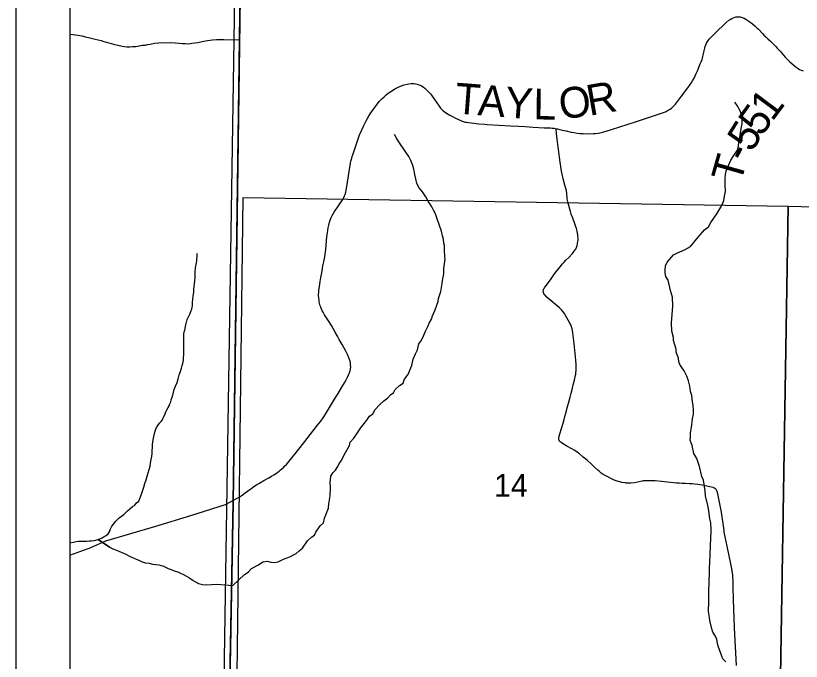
# Model space of a CAD drawing. Extents: x -1.2 to 34, y -8.5 to 22.
# Drawn here: x 2 to 3.451, y 15.827 to 17.02 of the extents above; entities that cross this region are included whole.
import ezdxf

# ---------------------------------------------------------------- set-up
doc = ezdxf.new("R2010")
doc.units = 0
for name, color, linetype in [('DV_X_County_Line', 7, 'Continuous'), ('GM_X_Minor_River', 7, 'Continuous'), ('GM_X_Section', 7, 'Continuous'), ('GM_X_Section_Text', 7, 'Continuous'), ('GM_X_Township_Road', 7, 'Continuous'), ('GM_X_Township_Road_Text', 7, 'Continuous'), ('GM_X_Unincorporated_Text', 7, 'Continuous'), ('SH_Cut_Line', 7, 'Continuous'), ('SH_Data', 7, 'Continuous')]:
    doc.layers.add(name, color=color, linetype=linetype)

msp = doc.modelspace()

# ---------------------------------------------------------------- linework, layer by layer
at = {"layer": 'DV_X_County_Line'}
msp.add_line((2.3586, 14.1), (2.465, 20.9), dxfattribs=at)
at = {"layer": 'GM_X_Minor_River'}
for points in [[(2.1, 16.9857), (2.106, 16.9851), (2.1147, 16.9841), (2.1223, 16.9827), (2.1292, 16.9809), (2.1368, 16.9794), (2.1421, 16.978), (2.1471, 16.9765), (2.1524, 16.9755), (2.1581, 16.974), (2.1631, 16.9726), (2.168, 16.9711), (2.1722, 16.97), (2.1764, 16.9689), (2.1806, 16.9675), (2.1966, 16.9639), (2.2008, 16.9631), (2.2053, 16.9628), (2.2107, 16.9629), (2.216, 16.9633), (2.2217, 16.9634), (2.2281, 16.9642), (2.2345, 16.9655), (2.2395, 16.9659), (2.2436, 16.9667), (2.2482, 16.9675), (2.2565, 16.9692), (2.2637, 16.97), (2.2709, 16.9705), (2.2781, 16.9702), (2.2861, 16.9703), (2.2944, 16.97), (2.302, 16.9693), (2.3081, 16.969), (2.313, 16.9687), (2.3184, 16.9684), (2.3222, 16.9688), (2.3256, 16.9693), (2.3309, 16.9697), (2.3366, 16.9705), (2.3445, 16.9722), (2.3543, 16.9742), (2.3638, 16.9754), (2.371, 16.9759), (2.3767, 16.9764), (2.3809, 16.9764), (2.3847, 16.9761), (2.4143, 16.9753)], [(3.2152, 16.4254), (3.212, 16.4375), (3.2117, 16.4528), (3.2126, 16.468), (3.2139, 16.4836), (3.2133, 16.5), (3.2097, 16.5121), (3.2057, 16.5315), (3.2014, 16.5383), (3.2002, 16.5451), (3.1997, 16.5504), (3.2007, 16.558), (3.2037, 16.5649), (3.2152, 16.5784), (3.2216, 16.5812), (3.2314, 16.5859), (3.237, 16.5883), (3.2468, 16.5938), (3.2609, 16.6107), (3.2725, 16.6242), (3.28, 16.6297), (3.2844, 16.6381), (3.2951, 16.6543), (3.3044, 16.6697), (3.308, 16.6785), (3.3094, 16.6869), (3.3112, 16.6953), (3.3106, 16.7074), (3.3105, 16.7192), (3.3111, 16.7269), (3.3125, 16.733), (3.3144, 16.738), (3.321, 16.7533), (3.3254, 16.7598), (3.3336, 16.7718), (3.3354, 16.7783), (3.336, 16.7866), (3.3371, 16.7916), (3.3385, 16.7992), (3.3406, 16.8115), (3.342, 16.8206), (3.3422, 16.8279), (3.3414, 16.8332), (3.3402, 16.8389), (3.3386, 16.8446), (3.3331, 16.854), (3.3285, 16.8604)], [(2.7375, 16.7268), (2.7355, 16.7363), (2.7335, 16.7431), (2.7303, 16.7526), (2.7261, 16.7598), (2.7206, 16.7677), (2.7171, 16.7737), (2.7117, 16.7817), (2.7079, 16.7869), (2.7028, 16.7948), (2.6997, 16.8005)], [(2.4012, 15.9674), (2.423, 15.9873), (2.4294, 15.9916), (2.4357, 15.9989), (2.4485, 16.0056), (2.4564, 16.011), (2.4651, 16.0123), (2.4711, 16.0105), (2.4784, 16.0098), (2.4851, 16.0111), (2.4945, 16.0158), (2.5017, 16.0182), (2.5077, 16.0206), (2.513, 16.0241), (2.5182, 16.0261), (2.5239, 16.0311), (2.5298, 16.0365), (2.5391, 16.0496), (2.5473, 16.0573), (2.5522, 16.0605), (2.5548, 16.0658), (2.5622, 16.0774), (2.5685, 16.0828), (2.5707, 16.0916), (2.574, 16.1008), (2.5776, 16.11), (2.5786, 16.118), (2.5807, 16.1332), (2.5816, 16.1477), (2.5811, 16.1576), (2.5814, 16.1629), (2.5824, 16.169), (2.5861, 16.1752), (2.5906, 16.1806), (2.5954, 16.1871), (2.5976, 16.1925), (2.6017, 16.1983), (2.6068, 16.2086), (2.6168, 16.2259), (2.6182, 16.232), (2.6249, 16.2393), (2.6316, 16.2493), (2.6372, 16.2578), (2.6446, 16.2671), (2.6502, 16.2744), (2.6535, 16.2801), (2.6599, 16.2844), (2.6643, 16.2925), (2.6725, 16.3014), (2.68, 16.3083), (2.6878, 16.3138), (2.6931, 16.3199), (2.6979, 16.3231), (2.7009, 16.3292), (2.7091, 16.3366), (2.7158, 16.3412), (2.718, 16.347), (2.7221, 16.3535), (2.7258, 16.3585), (2.7284, 16.365), (2.7317, 16.3735), (2.7345, 16.3853), (2.7385, 16.3956), (2.7422, 16.4026), (2.7451, 16.4136), (2.7484, 16.4186), (2.7528, 16.4267), (2.7569, 16.4374), (2.762, 16.447), (2.7638, 16.452), (2.7679, 16.4593), (2.7701, 16.4654), (2.7748, 16.4765), (2.7807, 16.4922), (2.7813, 16.4976), (2.7857, 16.5102), (2.7881, 16.5251), (2.7884, 16.5308), (2.7909, 16.543), (2.7911, 16.5529), (2.7932, 16.5705), (2.7931, 16.5754), (2.7925, 16.5872), (2.7924, 16.5952), (2.7912, 16.6001), (2.7904, 16.6066), (2.7884, 16.6134), (2.7864, 16.6221), (2.7832, 16.6327), (2.7788, 16.6445), (2.7753, 16.6539), (2.7722, 16.6607), (2.769, 16.6672), (2.7659, 16.6721), (2.7621, 16.6773), (2.7578, 16.6853), (2.7516, 16.6947), (2.7454, 16.7022), (2.7408, 16.7101), (2.7395, 16.7185), (2.7375, 16.7268)], [(2.2523, 16.2162), (2.2526, 16.2227), (2.2529, 16.228), (2.2532, 16.2318), (2.2539, 16.2363), (2.255, 16.2424), (2.2564, 16.2478), (2.2575, 16.2523), (2.259, 16.2562), (2.2604, 16.2592), (2.2619, 16.2619), (2.2638, 16.2646), (2.266, 16.2676), (2.2686, 16.2703), (2.2705, 16.2726), (2.2716, 16.2746), (2.2727, 16.2772), (2.2746, 16.2814), (2.276, 16.2845), (2.2775, 16.2879), (2.2793, 16.2917), (2.2816, 16.2963), (2.2834, 16.2994), (2.2849, 16.3028), (2.2864, 16.3066), (2.2874, 16.3104), (2.2889, 16.3154), (2.2907, 16.3211), (2.2925, 16.3291), (2.2954, 16.3356), (2.298, 16.3425), (2.3002, 16.349), (2.302, 16.3562), (2.3042, 16.3627), (2.306, 16.3688), (2.3078, 16.3738), (2.3089, 16.3776), (2.3093, 16.3806), (2.31, 16.3837), (2.3103, 16.3878), (2.3106, 16.3932), (2.3105, 16.3973), (2.3105, 16.4027), (2.3104, 16.408), (2.3107, 16.4141), (2.3104, 16.4323), (2.3115, 16.4357), (2.3123, 16.4388), (2.3133, 16.443), (2.3144, 16.4487), (2.3155, 16.4536), (2.3169, 16.459), (2.3191, 16.4639), (2.3217, 16.4685), (2.3232, 16.4716), (2.3243, 16.4754), (2.3254, 16.4781), (2.3261, 16.4811), (2.3264, 16.4849), (2.3268, 16.4879), (2.3267, 16.4906), (2.327, 16.4959), (2.3277, 16.502), (2.3288, 16.5085), (2.3294, 16.5142), (2.3298, 16.5199), (2.3304, 16.5248), (2.3311, 16.5302), (2.3314, 16.5362), (2.3313, 16.5419), (2.3317, 16.5476), (2.3323, 16.5537), (2.3326, 16.5579), (2.3334, 16.5606), (2.3341, 16.5636), (2.3344, 16.5671), (2.3348, 16.5701), (2.3351, 16.5739), (2.3354, 16.5777), (2.3354, 16.5804), (2.3358, 16.5811)], [(3.3117, 15.8262), (3.3064, 15.8315), (3.3044, 15.8368), (3.3001, 15.8481), (3.2981, 15.8553), (3.2968, 15.8606), (3.2952, 15.8675), (3.2932, 15.8739), (3.2882, 15.8807), (3.2859, 15.8871), (3.2826, 15.9023), (3.2821, 15.908), (3.2797, 15.919), (3.2806, 15.938), (3.2807, 15.9567), (3.2812, 15.9723), (3.2811, 15.9772), (3.2817, 15.9887), (3.2816, 15.9951), (3.2825, 16.0138), (3.2828, 16.021), (3.2836, 16.0435), (3.2842, 16.0523), (3.2851, 16.0702), (3.2841, 16.0831), (3.2825, 16.0907), (3.2808, 16.1048), (3.2792, 16.1123), (3.2747, 16.1328), (3.2738, 16.142), (3.2705, 16.1617), (3.2677, 16.1685), (3.2633, 16.1871), (3.2582, 16.2019), (3.2531, 16.2109), (3.2499, 16.2257), (3.2459, 16.2355), (3.2466, 16.2413), (3.2469, 16.2496), (3.2486, 16.2592), (3.2503, 16.2752), (3.2521, 16.284), (3.2523, 16.2905), (3.2518, 16.3007), (3.2506, 16.3064), (3.2493, 16.3186), (3.2469, 16.3258), (3.2452, 16.3353), (3.2428, 16.3455), (3.24, 16.3542), (3.235, 16.3637), (3.2307, 16.3701), (3.2272, 16.3757), (3.2253, 16.3806), (3.2244, 16.3871), (3.2205, 16.3985), (3.22, 16.4042), (3.2156, 16.4201), (3.2152, 16.4254)], [(2.1, 16.0461), (2.1066, 16.0473), (2.1119, 16.0485), (2.1157, 16.0489), (2.1198, 16.0489), (2.1252, 16.049), (2.1305, 16.0494), (2.1358, 16.0495), (2.1399, 16.0499), (2.1445, 16.0504), (2.1479, 16.0512), (2.1509, 16.052), (2.1555, 16.0536), (2.1596, 16.0551), (2.1634, 16.0575), (2.1671, 16.0598), (2.1709, 16.0625), (2.1731, 16.0667), (2.1749, 16.0717), (2.1775, 16.0766), (2.1813, 16.0812), (2.1839, 16.0851), (2.1872, 16.0885), (2.1914, 16.092), (2.1955, 16.0955), (2.1996, 16.0986), (2.203, 16.1016), (2.2067, 16.1051), (2.2109, 16.1089), (2.2157, 16.1132), (2.2203, 16.1159), (2.2232, 16.1197), (2.2274, 16.1228), (2.2292, 16.1278), (2.231, 16.1327), (2.2329, 16.1377), (2.2351, 16.1434), (2.2369, 16.1492), (2.2387, 16.156), (2.2409, 16.1625), (2.2431, 16.169), (2.2485, 16.1877), (2.2492, 16.1934), (2.2502, 16.1998), (2.2513, 16.2059), (2.252, 16.2109), (2.2523, 16.2162)], [(2.1735, 16.0378), (2.1525, 16.0525), (2.1735, 16.0378), (2.1792, 16.0352), (2.1865, 16.0323), (2.1949, 16.0286), (2.2033, 16.0249), (2.2105, 16.0212), (2.2167, 16.0182), (2.2224, 16.016), (2.2273, 16.0138), (2.2338, 16.0109), (2.2396, 16.0094), (2.2464, 16.0084), (2.2529, 16.0069), (2.259, 16.0059), (2.2643, 16.0052), (2.2689, 16.0041), (2.273, 16.003), (2.2765, 16.0011), (2.2814, 15.9989), (2.2875, 15.9967), (2.2929, 15.9945), (2.2997, 15.9927), (2.3047, 15.9901), (2.3101, 15.9875), (2.3154, 15.9845), (2.3196, 15.9819), (2.3235, 15.9793), (2.3277, 15.9767), (2.3323, 15.9737), (2.3376, 15.9711), (2.3449, 15.9693), (2.3517, 15.9687), (2.3718, 15.9697), (2.4012, 15.9674)]]:
    msp.add_lwpolyline(points, dxfattribs=at)
at = {"layer": 'GM_X_Section'}
for points in [[(3.4269, 16.668), (3.4107, 15.6483), (2.4074, 15.6568), (2.4204, 16.684)], [(3.4269, 16.668), (4.4375, 16.6421), (4.4223, 15.6306), (3.4107, 15.6483)]]:
    msp.add_lwpolyline(points, close=True, dxfattribs=at)
at = {"layer": 'GM_X_Township_Road'}
for points in [[(2.8366, 16.8228), (2.8463, 16.8216), (2.8509, 16.8211), (2.8559, 16.8205), (2.8665, 16.8194), (2.8712, 16.819), (2.9141, 16.8168), (2.9288, 16.8161), (2.9414, 16.8154), (2.9559, 16.8143), (2.9765, 16.8132), (2.9878, 16.8127), (2.9909, 16.8124), (2.9943, 16.812), (2.9988, 16.8113), (3.0012, 16.8109), (3.0096, 16.8089), (3.0171, 16.8071), (3.026, 16.8052), (3.0319, 16.804), (3.0371, 16.8032), (3.0422, 16.8026), (3.0484, 16.8023), (3.0587, 16.802), (3.0673, 16.8023), (3.0714, 16.8026), (3.0761, 16.8032), (3.082, 16.8042), (3.0846, 16.8048), (3.1007, 16.8099), (3.147, 16.8249), (3.1858, 16.8375), (3.1929, 16.8398), (3.1987, 16.8419), (3.2018, 16.8434), (3.2056, 16.8454), (3.209, 16.8475), (3.2116, 16.8494), (3.2142, 16.8517), (3.2166, 16.8543), (3.2187, 16.8567), (3.2298, 16.8713), (3.2437, 16.8893), (3.2462, 16.8927), (3.2481, 16.8954), (3.2504, 16.8996), (3.2532, 16.9048), (3.2571, 16.9132), (3.2595, 16.9184), (3.2648, 16.9311), (3.2664, 16.9351), (3.268, 16.9393), (3.2687, 16.9417), (3.2694, 16.9445), (3.2701, 16.9474), (3.2711, 16.9526), (3.2731, 16.9601), (3.2738, 16.9631), (3.2749, 16.966), (3.2762, 16.9691), (3.2779, 16.9723), (3.2794, 16.9746), (3.2809, 16.9765), (3.283, 16.9788), (3.2945, 16.9901), (3.3093, 17.0046), (3.3118, 17.0068), (3.3177, 17.0117), (3.32, 17.0133), (3.3228, 17.0149), (3.3245, 17.0158), (3.3276, 17.017), (3.3304, 17.0178), (3.3329, 17.0182), (3.3346, 17.0183), (3.3385, 17.018), (3.3402, 17.0177), (3.3443, 17.0164), (3.3461, 17.0156), (3.3509, 17.0127), (3.3544, 17.0102), (3.3611, 17.0048), (3.366, 17.0007), (3.3695, 16.998), (3.3723, 16.9952), (3.3797, 16.9873), (3.3825, 16.9843), (3.3858, 16.9808), (3.3898, 16.9772), (3.3943, 16.9729), (3.3995, 16.9681), (3.4036, 16.9639), (3.4071, 16.9601), (3.4098, 16.9573), (3.4123, 16.9546), (3.4218, 16.9438), (3.4266, 16.9385), (3.4304, 16.9347), (3.434, 16.9315), (3.4386, 16.9276), (3.442, 16.925), (3.4456, 16.9225), (3.4482, 16.921), (3.4512, 16.9196), (3.4547, 16.9184)], [(2.4104, 16.1292), (2.4145, 16.1317), (2.4186, 16.1343), (2.4241, 16.1383), (2.4324, 16.1447), (2.4341, 16.146), (2.4397, 16.15), (2.4449, 16.1534), (2.4504, 16.1564), (2.4583, 16.161), (2.4675, 16.1662), (2.4727, 16.1691), (2.4772, 16.1719), (2.4802, 16.1738), (2.4867, 16.1784), (2.4888, 16.1801), (2.4947, 16.1853), (2.4975, 16.1881), (2.5003, 16.1911), (2.5028, 16.1941), (2.5254, 16.2225), (2.5578, 16.2636), (2.5636, 16.271), (2.5681, 16.2769), (2.5724, 16.2838), (2.5799, 16.2964), (2.5892, 16.3117), (2.5957, 16.3223), (2.6027, 16.334), (2.6075, 16.342), (2.6103, 16.3471), (2.6131, 16.3521), (2.6157, 16.3576), (2.6169, 16.3605), (2.618, 16.3639), (2.6187, 16.3677), (2.6189, 16.371), (2.6188, 16.375), (2.6183, 16.3785), (2.6177, 16.3819), (2.6168, 16.3851), (2.6157, 16.3881), (2.6134, 16.3931), (2.6091, 16.4014), (2.6031, 16.4125), (2.5978, 16.4219), (2.5944, 16.4281), (2.5903, 16.4354), (2.5864, 16.4422), (2.5832, 16.4474), (2.5789, 16.4542), (2.5739, 16.462), (2.5705, 16.4676), (2.5679, 16.4722), (2.5664, 16.4749), (2.5635, 16.4818), (2.5627, 16.484), (2.562, 16.4866), (2.5608, 16.4916), (2.5604, 16.4941), (2.5599, 16.4986), (2.5597, 16.5032), (2.5599, 16.5102), (2.5601, 16.513), (2.5612, 16.5199), (2.5627, 16.5288), (2.564, 16.5363), (2.5649, 16.5421), (2.5661, 16.5487), (2.5677, 16.5578), (2.5693, 16.5654), (2.571, 16.5745), (2.5729, 16.5884), (2.5736, 16.5962), (2.5743, 16.6039), (2.5751, 16.6124), (2.5758, 16.6189), (2.5765, 16.6241), (2.5772, 16.6283), (2.5783, 16.6331), (2.5797, 16.6389), (2.581, 16.6425), (2.5829, 16.6473), (2.5839, 16.6494), (2.5864, 16.6542), (2.5891, 16.6585), (2.59, 16.66), (2.5939, 16.6653), (2.6016, 16.6764), (2.6044, 16.6808), (2.6064, 16.6842), (2.6077, 16.6871), (2.6087, 16.69), (2.6098, 16.6941), (2.6106, 16.6978), (2.6113, 16.7011), (2.6131, 16.7126), (2.6148, 16.7243), (2.6186, 16.7476), (2.6194, 16.7514), (2.6209, 16.7567), (2.6219, 16.7598), (2.6236, 16.7649), (2.632, 16.7908), (2.6338, 16.7962), (2.6352, 16.7998), (2.6363, 16.8023), (2.6425, 16.8157), (2.6482, 16.8272), (2.6505, 16.8314), (2.655, 16.8388), (2.6591, 16.8451), (2.6632, 16.8507), (2.6678, 16.8566), (2.6723, 16.8619), (2.6767, 16.8666), (2.6806, 16.8703), (2.6845, 16.8737), (2.6883, 16.8768), (2.6929, 16.88), (2.6959, 16.8819), (2.7005, 16.8847), (2.7052, 16.8873), (2.7099, 16.8895), (2.7141, 16.8912), (2.7175, 16.8924), (2.7234, 16.8939), (2.7262, 16.8944), (2.7304, 16.8949), (2.7361, 16.8947), (2.7389, 16.8942), (2.7419, 16.8935), (2.7448, 16.8926), (2.7475, 16.8915), (2.7498, 16.8903), (2.753, 16.8884), (2.7556, 16.8864), (2.7586, 16.8837), (2.7611, 16.8811), (2.7637, 16.8784), (2.7661, 16.8756), (2.7681, 16.8731), (2.7738, 16.8651), (2.7822, 16.8527), (2.7847, 16.8494), (2.7867, 16.8472), (2.7884, 16.8457), (2.7918, 16.843), (2.7959, 16.8403), (2.8021, 16.8364), (2.8082, 16.8331), (2.8124, 16.8309), (2.8223, 16.8264), (2.825, 16.8253), (2.8306, 16.8237), (2.8327, 16.8233), (2.8366, 16.8228)], [(3.245, 16.1552), (3.244, 16.1553), (3.2371, 16.1557), (3.2313, 16.1558), (3.2256, 16.1561), (3.2211, 16.1564), (3.1933, 16.1595), (3.1815, 16.1607), (3.178, 16.1609), (3.164, 16.1606), (3.1595, 16.1604), (3.1573, 16.16), (3.1542, 16.1593), (3.152, 16.1588), (3.1462, 16.1575), (3.143, 16.1569), (3.1363, 16.1564), (3.1336, 16.1563), (3.128, 16.1565), (3.1263, 16.1567), (3.12, 16.1578), (3.1164, 16.1586), (3.1113, 16.16), (3.1096, 16.1606), (3.1045, 16.1627), (3.1008, 16.1645), (3.0937, 16.1682), (3.0879, 16.1713), (3.0856, 16.1726), (3.0817, 16.1751), (3.0785, 16.1776), (3.0756, 16.1802), (3.0693, 16.1859), (3.063, 16.1918), (3.0564, 16.1979), (3.0487, 16.2045), (3.0419, 16.2103), (3.0398, 16.2119), (3.0373, 16.2136), (3.033, 16.2165), (3.0274, 16.2197), (3.0184, 16.225), (3.0101, 16.2299), (3.007, 16.2318), (3.0058, 16.2329), (3.0048, 16.2341), (3.0042, 16.2355), (3.0036, 16.2368), (3.0034, 16.2378), (3.0032, 16.2389), (3.0039, 16.2433), (3.0054, 16.2476), (3.0086, 16.2575), (3.0114, 16.2669), (3.0134, 16.2741), (3.0148, 16.2793), (3.0164, 16.2857), (3.0175, 16.2898), (3.0189, 16.2955), (3.02, 16.3), (3.0224, 16.3085), (3.0244, 16.3154), (3.0263, 16.3224), (3.0287, 16.3316), (3.0302, 16.3378), (3.0313, 16.3422), (3.0323, 16.3466), (3.0331, 16.35), (3.0339, 16.3535), (3.0348, 16.3577), (3.035, 16.3594), (3.0354, 16.3652), (3.0356, 16.3718), (3.0355, 16.3758), (3.035, 16.3836), (3.0345, 16.3897), (3.0339, 16.3962), (3.032, 16.4145), (3.0296, 16.434), (3.0289, 16.4384), (3.028, 16.4417), (3.027, 16.4449), (3.0255, 16.4487), (3.0238, 16.4521), (3.0154, 16.4675), (3.014, 16.4696), (3.0117, 16.4727), (3.0084, 16.4766), (3.0058, 16.4793), (3.0046, 16.4803), (2.982, 16.4994), (2.981, 16.5003), (2.9773, 16.5041), (2.9765, 16.5052), (2.9755, 16.507), (2.9751, 16.5084), (2.9748, 16.5108), (2.975, 16.513), (2.9754, 16.5145), (2.9761, 16.5159), (2.9769, 16.5173), (2.989, 16.534), (2.9956, 16.5429), (3.0057, 16.5559), (3.0101, 16.5614), (3.0124, 16.5641), (3.0166, 16.5684), (3.0218, 16.5736), (3.0286, 16.5808), (3.03, 16.5825), (3.0339, 16.5877), (3.0346, 16.5889), (3.0368, 16.5937), (3.0374, 16.5955), (3.0382, 16.599), (3.0387, 16.603), (3.0389, 16.6062), (3.0385, 16.6157), (3.0382, 16.6174), (3.0371, 16.622), (3.0358, 16.6268), (3.0343, 16.632), (3.0331, 16.6354), (3.0291, 16.6461), (3.0265, 16.6533), (3.0248, 16.6585), (3.0204, 16.6739), (3.0199, 16.6761), (3.0192, 16.6793), (3.0188, 16.682), (3.0187, 16.6861), (3.0185, 16.6883), (3.0182, 16.6928), (3.0179, 16.6946), (3.0174, 16.6972), (3.0171, 16.699), (3.0166, 16.7007), (3.0148, 16.7069), (3.0114, 16.7189), (3.0107, 16.7217), (3.0095, 16.7274), (3.0085, 16.733), (3.0078, 16.737), (3.0061, 16.7497), (3.0026, 16.7731), (3.002, 16.7772), (3.0003, 16.7921), (2.9994, 16.8023), (2.9988, 16.8113)], [(3.3319, 15.8191), (3.3282, 15.8891), (3.3274, 15.9075), (3.3263, 15.941), (3.3258, 15.9654), (3.3256, 15.9737), (3.3251, 15.984), (3.3249, 15.9865), (3.3224, 16.0018), (3.3214, 16.0073), (3.3145, 16.0397), (3.3091, 16.0659), (3.3087, 16.0686), (3.3037, 16.1027), (3.3033, 16.1056), (3.2977, 16.1334), (3.2964, 16.1391), (3.2957, 16.1412), (3.2948, 16.1432), (3.2939, 16.1446), (3.2928, 16.1458), (3.2912, 16.147), (3.2892, 16.148), (3.2883, 16.1484), (3.2856, 16.1491), (3.2793, 16.1503), (3.2718, 16.1518), (3.2604, 16.1537), (3.2543, 16.1545), (3.2496, 16.1549), (3.245, 16.1552)], [(2.1442, 16.0399), (2.1667, 16.05), (2.259, 16.0769), (2.3234, 16.0964), (2.3874, 16.117), (2.4104, 16.1292)], [(2.1, 16.023), (2.1338, 16.0353), (2.1346, 16.0356), (2.1442, 16.0399)]]:
    msp.add_lwpolyline(points, dxfattribs=at)
at = {"layer": 'GM_X_Unincorporated_Text'}
for p, q in [((2.1, 20.6871), (2.1, 14.6393)), ((2.4189, 17.3824), (2.402, 16.1209)), ((2.402, 16.1209), (2.4189, 17.3824)), ((2.402, 16.1209), (2.3867, 15.3183)), ((2.3867, 15.3183), (2.402, 16.1209))]:
    msp.add_line(p, q, dxfattribs=at)
at = {"layer": 'SH_Cut_Line'}
msp.add_lwpolyline([(2.465, 20.9), (2.1, 20.9), (2.1, 14.1), (2.3586, 14.1), (2.3643, 14.4203), (2.3672, 14.6322), (2.3867, 15.3183), (2.402, 16.1209), (2.4189, 17.3824), (2.4258, 17.6899), (2.4414, 19.0677), (2.4628, 20.1657), (2.4644, 20.6742)], close=True, dxfattribs=at)
msp.add_lwpolyline([(4.6867, 17.6371), (4.4093, 17.6489), (4.1759, 17.654), (3.3984, 17.6707), (2.8968, 17.6806), (2.4258, 17.6899), (2.4189, 17.3824), (2.402, 16.1209), (2.3867, 15.3183), (2.3672, 14.6322), (2.3643, 14.4203), (2.3586, 14.1), (8.9, 14.1)], dxfattribs=at)
at = {"layer": 'SH_Data'}
for p, q in [((2, 21), (2, 14)), ((2, 21), (2, 14)), ((2.1, 20.9), (2.1, 14.1)), ((2.1, 20.9), (2.1, 14.1))]:
    msp.add_line(p, q, dxfattribs=at)

# ---------------------------------------------------------------- texts
at = {"layer": 'GM_X_Section_Text'}
msp.add_text('14', height=0.04186, rotation=0, dxfattribs=at).set_placement((2.8836, 16.1312))
at = {"layer": 'GM_X_Township_Road_Text'}
for s, rotation, p in [('T', 355.5643, (2.81, 16.8398)), ('R', 9.9526, (3.0598, 16.8349)), ('A', 355.567, (2.8524, 16.8365)), ('Y', 355.6374, (2.9023, 16.8326)), ('L', 359.1814, (2.956, 16.8286)), ('O', 6.8929, (3.0069, 16.8285)), ('1', 53.3476, (3.3976, 16.8231)), ('5', 54.4052, (3.3774, 16.7948)), ('5', 58.4436, (3.3597, 16.7659)), ('T', 74.1205, (3.3391, 16.708)), ('-', 62.9357, (3.3496, 16.7461))]:
    msp.add_text(s, height=0.0568, rotation=rotation, dxfattribs=at).set_placement(p)

doc.saveas('drawing.dxf')
